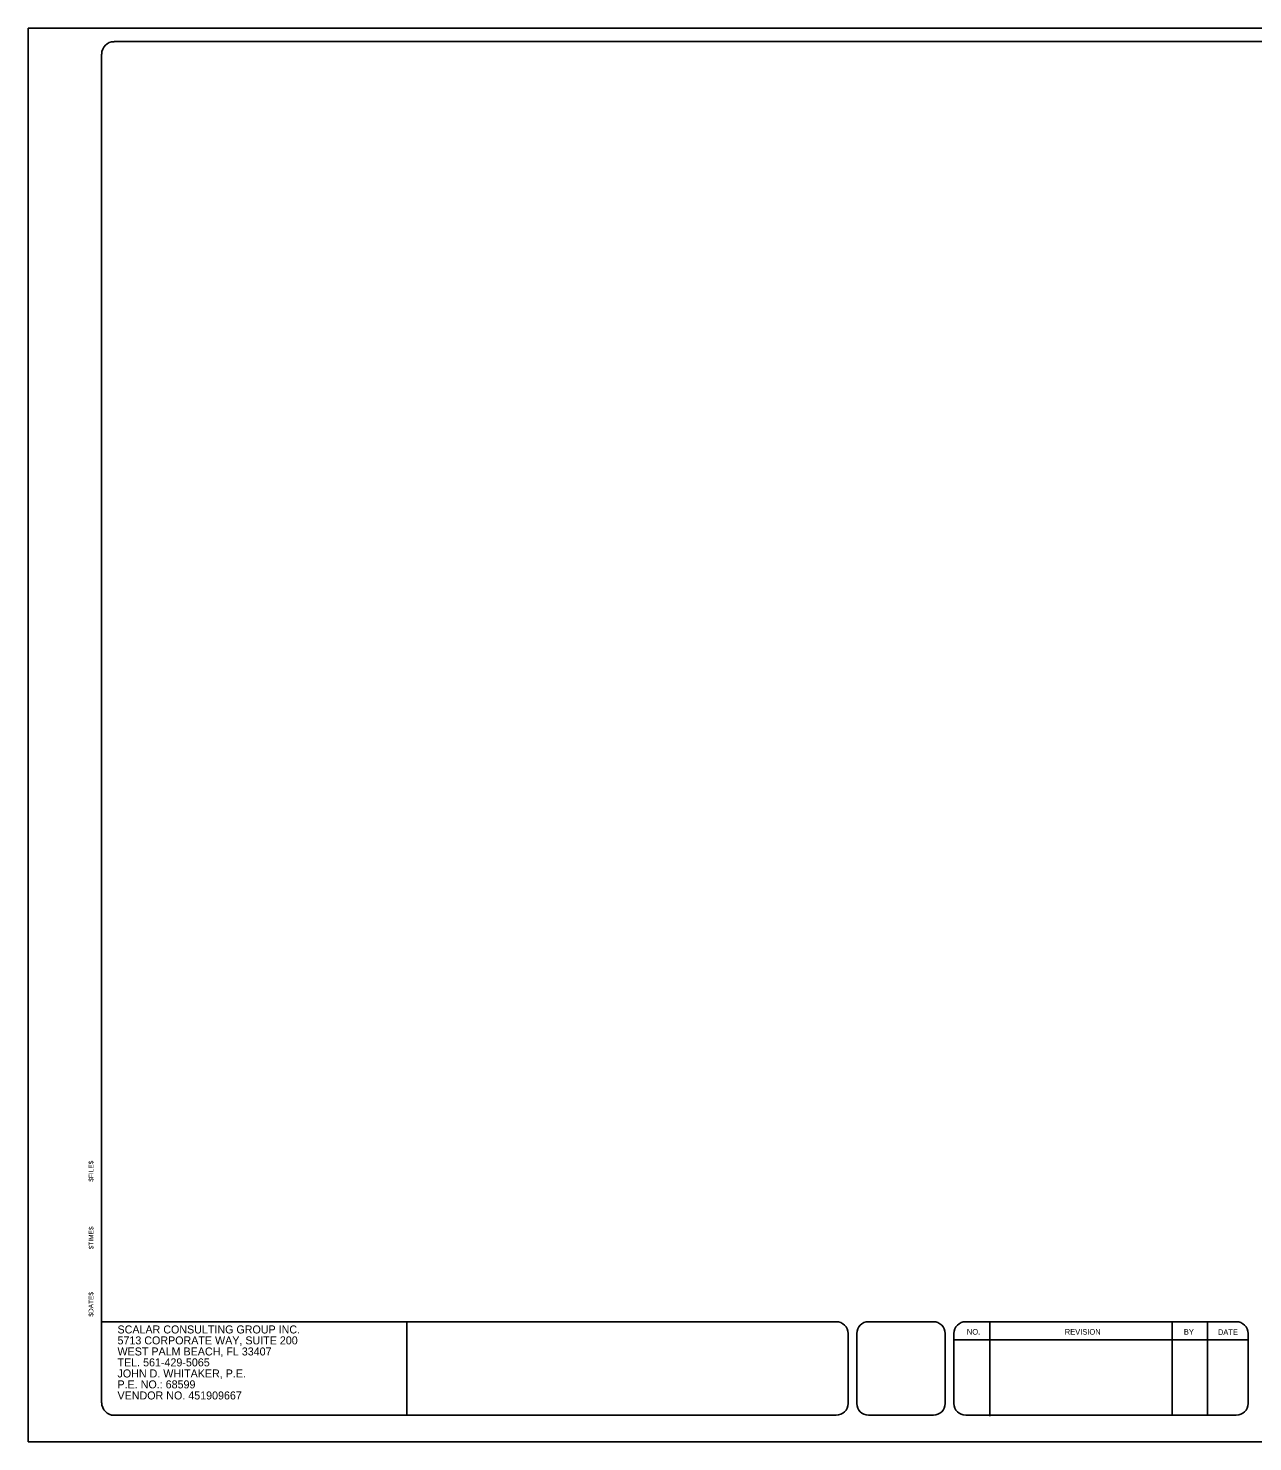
# Model space of a CAD drawing. Extents: x -0.6 to 16, y -0.9 to 9.7.
# Drawn here: x -0.55 to 8.63, y -0.9 to 9.7 of the extents above; entities that cross this region are included whole.
import ezdxf

# ---------------------------------------------------------------- set-up
doc = ezdxf.new("R2010")
doc.units = 0
doc.layers.add('Default', color=7, linetype='Continuous')
doc.layers.add('PlotBorder_dp', color=7, linetype='Continuous')

msp = doc.modelspace()

# ---------------------------------------------------------------- linework, layer by layer
at = {"layer": 'Default'}
for p, q in [((15.325, 9.6), (0.094, 9.6)), ((0, -0.608), (0, 9.506)), ((5.508, 0), (0, 0)), ((6.236, 0), (5.75, 0)), ((8.507, 0), (6.478, 0)), ((2.289, -0.701), (2.289, 0)), ((5.596, -0.088), (5.596, -0.613)), ((5.662, -0.088), (5.662, -0.613)), ((6.324, -0.088), (6.324, -0.613)), ((6.39, -0.088), (6.39, -0.613)), ((6.658, -0.004), (6.658, -0.709)), ((8.025, -0.004), (8.025, -0.7)), ((8.29, -0.004), (8.29, -0.7)), ((8.595, -0.088), (8.595, -0.613)), ((8.599, -0.136), (6.393, -0.136)), ((5.508, -0.701), (0.093, -0.701)), ((6.236, -0.701), (5.75, -0.701)), ((8.507, -0.701), (6.478, -0.701))]:
    msp.add_line(p, q, dxfattribs=at)
for centre, major_axis, start_param, end_param in [((0.094, 9.506), (0, -0.0935), 3.141593, 4.712389), ((5.508, -0.088), (0, 0.0882), 4.712389, 6.283185), ((5.75, -0.088), (0, 0.0882), 0, 1.570796), ((6.236, -0.088), (0, 0.0882), 4.712389, 6.283185), ((6.478, -0.088), (0, 0.0882), 0, 1.570796), ((8.507, -0.088), (0, 0.0882), 4.712389, 6.283185), ((0.094, -0.608), (0, -0.0935), 4.712389, 6.283185), ((5.508, -0.613), (0, 0.0882), 3.141593, 4.712389), ((5.75, -0.613), (0, -0.0882), 4.712389, 6.283185), ((6.236, -0.613), (0, 0.0882), 3.141593, 4.712389), ((6.478, -0.613), (0, -0.0882), 4.712389, 6.283185), ((8.507, -0.613), (0, 0.0882), 3.141593, 4.712389)]:
    msp.add_ellipse(centre, major_axis=major_axis, ratio=0.999927, start_param=start_param, end_param=end_param, dxfattribs=at)
at = {"layer": 'PlotBorder_dp'}
msp.add_lwpolyline([(-0.55, -0.9), (15.95, -0.9), (15.95, 9.7), (-0.55, 9.7)], close=True, dxfattribs=at)

# ---------------------------------------------------------------- texts
at = {"layer": 'Default'}
for s, p in [('$FILE$', (-0.062, 1.05)), ('$TIME$', (-0.061, 0.543)), ('$DATE$', (-0.062, 0.038))]:
    msp.add_text(s, height=0.0354, rotation=90, dxfattribs=at).set_placement(p)
for s, height, p in [('SCALAR CONSULTING GROUP INC.', 0.06, (0.119, -0.088)), ('NO.', 0.0421, (6.487, -0.097)), ('REVISION', 0.0421, (7.221, -0.097)), ('BY', 0.0421, (8.114, -0.097)), ('DATE', 0.0421, (8.369, -0.099)), ('WEST PALM BEACH, FL 33407', 0.06, (0.119, -0.253)), ('5713 CORPORATE WAY, SUITE 200', 0.06, (0.119, -0.17)), ('TEL. 561-429-5065', 0.06, (0.119, -0.335)), ('JOHN D. WHITAKER, P.E.', 0.06, (0.119, -0.418)), ('VENDOR NO. 451909667', 0.06, (0.119, -0.583)), ('P.E. NO.: 68599', 0.06, (0.119, -0.5))]:
    msp.add_text(s, height=height, dxfattribs=at).set_placement(p)

doc.saveas('drawing.dxf')
